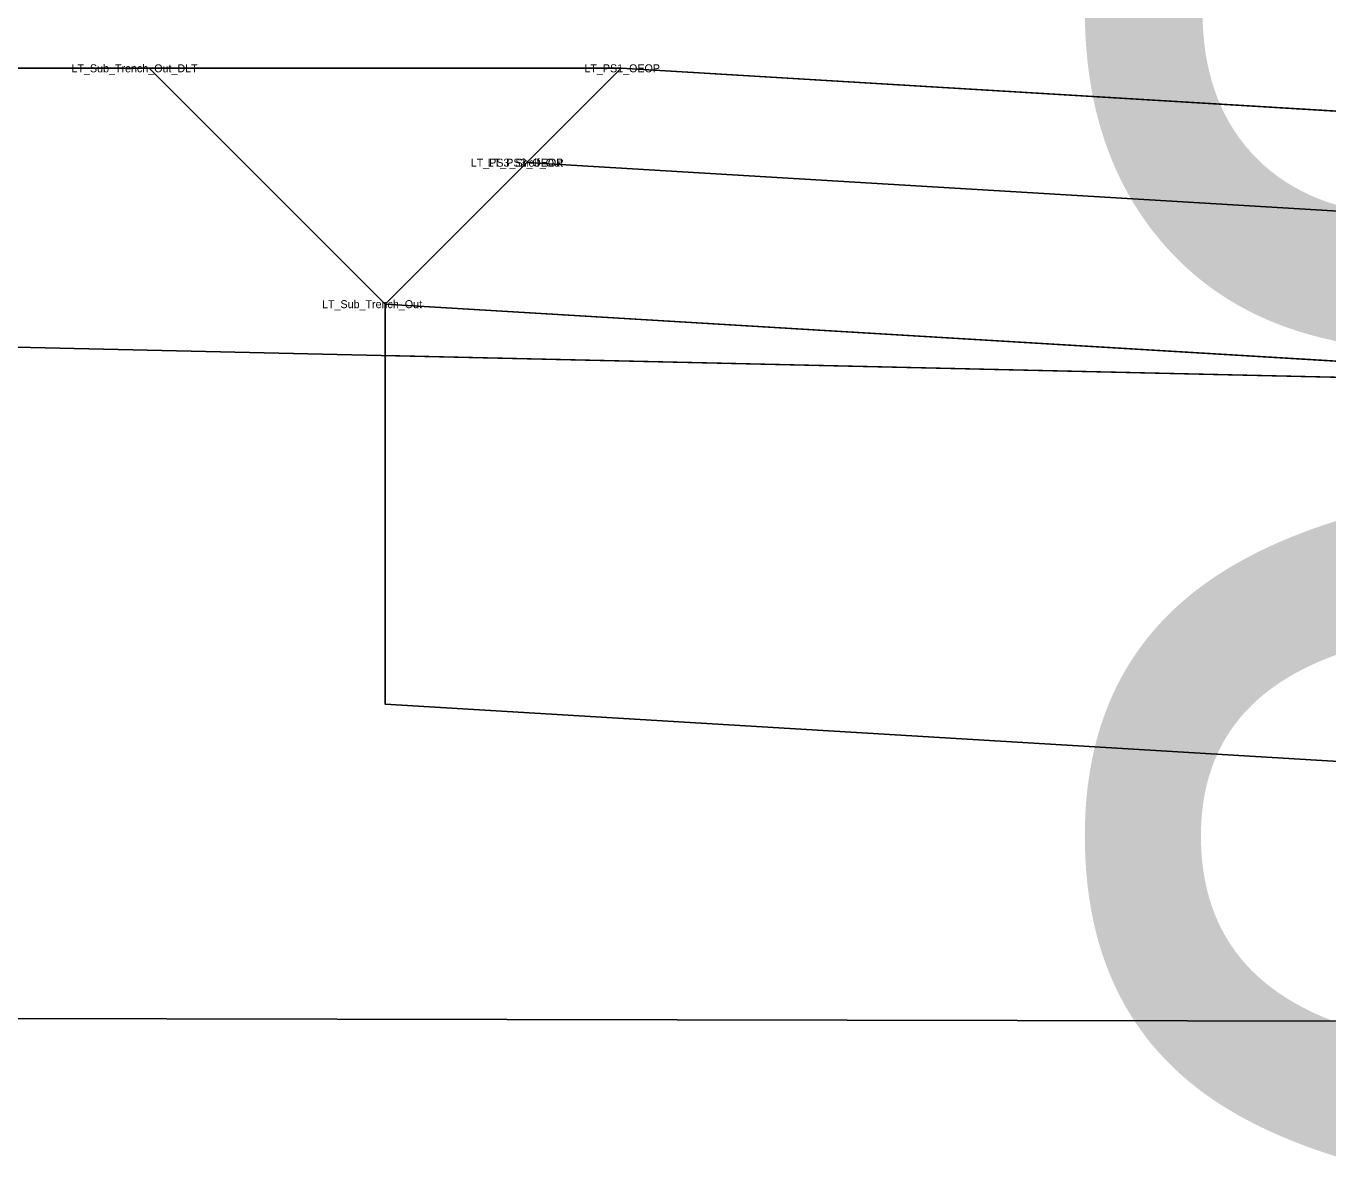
# Model space of a CAD drawing. Extents: x -516 to 303, y -10 to 5017.
# Drawn here: x 144.513 to 147.766, y 3502.271 to 3505.146 of the extents above; entities that cross this region are included whole.
import ezdxf

# ---------------------------------------------------------------- set-up
doc = ezdxf.new("R2010")
doc.units = 0
for name, color, linetype in [('Exist Cross Section Cell', 7, 'Continuous'), ('Exist XS Ground Line', 7, 'Continuous'), ('Prop CMT Pvmt Surface Shoulder', 7, 'Continuous'), ('Prop CMT Shld Paved Course 1', 7, 'Continuous'), ('Prop CMT Shld Paved Course 2', 7, 'Continuous'), ('Prop CMT Shld Paved Course 3', 7, 'Continuous'), ('Prop CMT Slope Grass', 7, 'Continuous'), ('Prop CMT Subgrade Earthwork', 7, 'Continuous'), ('Prop Road Sect_ Material - Contact (General - Major)', 7, 'Continuous'), ('Prop Road Sect_ Misc - Drafting Aid (solid line)', 7, 'Continuous'), ('Prop Road Sect_ Recs - UC Shallow (Outline)', 7, 'Continuous'), ('Prop Road Sect_ Recs - UC Shallow (Pattern)', 7, 'Continuous'), ('Scratch_Level_0', 7, 'Continuous')]:
    doc.layers.add(name, color=color, linetype=linetype)

msp = doc.modelspace()

# ---------------------------------------------------------------- linework, layer by layer
at = {"layer": 'Exist XS Ground Line'}
msp.add_lwpolyline([(125.205, 3503.8945), (131.7518, 3504.2176), (136.6829, 3504.4743), (138.318, 3504.4836), (148.612, 3504.249), (149.068, 3504.2286), (150, 3504.197), (151.3235, 3504.1521), (153.2258, 3504.1006), (154.2229, 3504.0743), (155.6813, 3504.0239), (157.1104, 3503.9729), (158.1124, 3503.9391), (159.3093, 3503.9003), (160.0118, 3503.8781), (163.151, 3503.7853), (163.5861, 3503.7651), (164.5345, 3503.7181), (165.9518, 3503.6102), (166.3074, 3503.5849)], dxfattribs=at)
at = {"layer": 'Prop CMT Pvmt Surface Shoulder'}
msp.add_line((148, 3504.92), (146, 3505.04), dxfattribs=at)
at = {"layer": 'Prop CMT Shld Paved Course 1'}
for points in [[(148, 3504.92), (146, 3505.04), (145.7642, 3504.8042)], [(145.7642, 3504.8042), (148, 3504.67)]]:
    msp.add_lwpolyline(points, dxfattribs=at)
at = {"layer": 'Prop CMT Shld Paved Course 2'}
for points in [[(148, 3504.67), (145.7642, 3504.8042)], [(145.7642, 3504.8042), (145.7642, 3504.8042)], [(145.7642, 3504.8042), (148, 3504.67)]]:
    msp.add_lwpolyline(points, dxfattribs=at)
at = {"layer": 'Prop CMT Shld Paved Course 3'}
for points in [[(145.7642, 3504.8042), (145.4104, 3504.4504)], [(148, 3504.67), (145.7642, 3504.8042)], [(145.7642, 3504.8042), (145.7642, 3504.8042)], [(145.4104, 3504.4504), (148, 3504.295)]]:
    msp.add_lwpolyline(points, dxfattribs=at)
at = {"layer": 'Prop CMT Slope Grass'}
msp.add_line((146, 3505.04), (140, 3505.04), dxfattribs=at)
at = {"layer": 'Prop CMT Subgrade Earthwork'}
for p, q in [((145.4104, 3504.4504), (144.8208, 3505.04)), ((148, 3504.295), (145.4104, 3504.4504))]:
    msp.add_line(p, q, dxfattribs=at)
at = {"layer": 'Prop Road Sect_ Material - Contact (General - Major)'}
msp.add_line((176.8467, 3502.6017), (116.479, 3502.7189), dxfattribs=at)
at = {"layer": 'Prop Road Sect_ Misc - Drafting Aid (solid line)'}
msp.add_line((145.4104, 3504.4504), (145.4104, 3503.4504), dxfattribs=at)
at = {"layer": 'Prop Road Sect_ Recs - UC Shallow (Outline)'}
msp.add_lwpolyline([(165.1941, 3503.3234), (165.1941, 3503.6679), (164.5345, 3503.7181), (163.5861, 3503.7651), (163.151, 3503.7853), (159.3093, 3503.9003), (158.1124, 3503.9391), (157.1104, 3503.9729), (155.6813, 3504.0239), (154.2229, 3504.0743), (151.3235, 3504.1521), (150, 3504.197), (149.068, 3504.2286), (148.612, 3504.249), (148.0014, 3504.2629), (145.4104, 3504.322), (145.4104, 3503.4504), (148, 3503.295), (161.5292, 3502.4832), (164.1941, 3502.3234), (165.1941, 3502.3234), (165.1941, 3503.3234)], dxfattribs=at)
at = {"layer": 'Prop Road Sect_ Recs - UC Shallow (Pattern)'}
msp.add_lwpolyline([(165.1941, 3503.3234), (165.1941, 3503.6679), (164.5345, 3503.7181), (163.5861, 3503.7651), (163.151, 3503.7853), (159.3093, 3503.9003), (158.1124, 3503.9391), (157.1104, 3503.9729), (155.6813, 3504.0239), (154.2229, 3504.0743), (151.3235, 3504.1521), (150, 3504.197), (149.068, 3504.2286), (148.612, 3504.249), (148.0014, 3504.2629), (145.4104, 3504.322), (145.4104, 3503.4504), (148, 3503.295), (161.5292, 3502.4832), (164.1941, 3502.3234), (165.1941, 3502.3234), (165.1941, 3503.3234)], dxfattribs=at)

# ---------------------------------------------------------------- texts
at = {"layer": 'Exist Cross Section Cell'}
msp.add_text('N 511503.2988', height=2.8, rotation=90, dxfattribs=at).set_placement((150, 3490))
at = {"layer": 'Scratch_Level_0'}
for s, p in [('LT_Sub_Trench_Out_DLT', (144.6264, 3505.03)), ('LT_PS1_OEOP', (145.908, 3505.03)), ('LT_PS3_Shelf_Out', (145.624, 3504.7942)), ('LT_PS3_OEOP', (145.6665, 3504.7942)), ('LT_PS2_OEOP', (145.6665, 3504.7942)), ('LT_Sub_Trench_Out', (145.2524, 3504.4404))]:
    msp.add_text(s, height=0.02, dxfattribs=at).set_placement(p)

doc.saveas('drawing.dxf')
